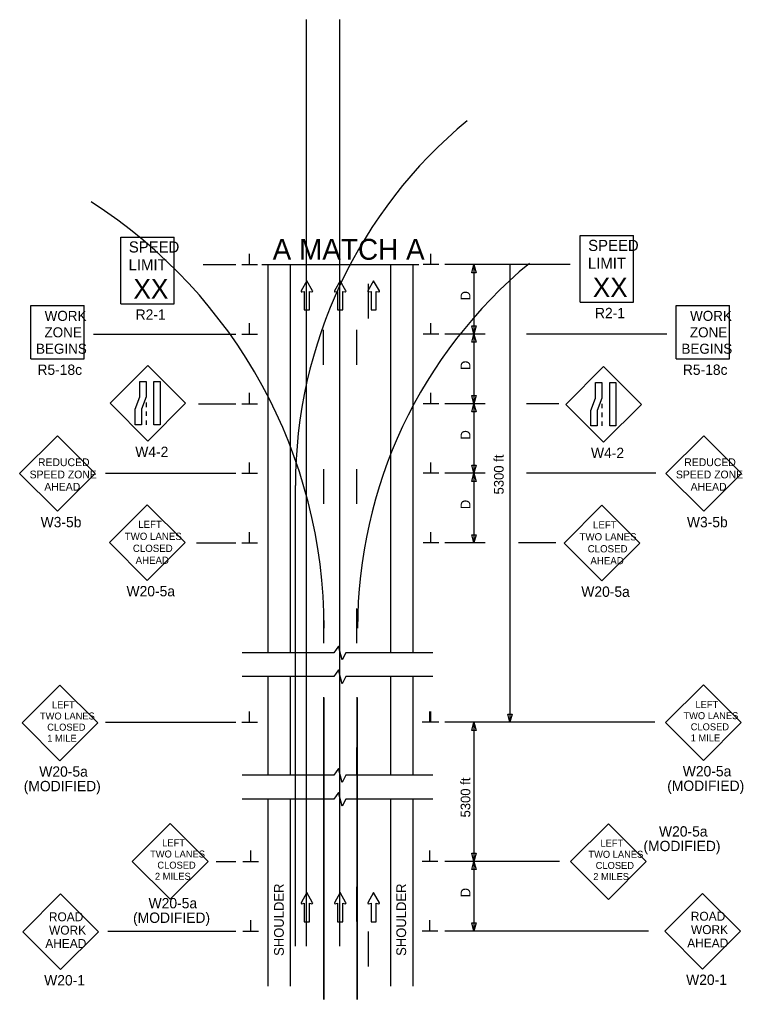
# Model space of a CAD drawing. Extents: x 16728 to 19504, y 5553 to 7079.
# Drawn here: x 17849 to 18369, y 6375 to 7079 of the extents above; entities that cross this region are included whole.
import ezdxf

# ---------------------------------------------------------------- set-up
doc = ezdxf.new("R2010")
doc.units = 0
for name, color, linetype in [('ALI_LEGAL_EX', 7, 'Continuous'), ('MT_SCRATCH_LEVEL_E', 7, 'Continuous'), ('PAVT_EDGE_EX', 7, 'Continuous'), ('TRAFFIC_SIGNS_PR', 7, 'Continuous'), ('TYPICAL_TEXT_DIMEN_PR', 7, 'Continuous')]:
    doc.layers.add(name, color=color, linetype=linetype)

msp = doc.modelspace()

# ---------------------------------------------------------------- linework, layer by layer
at = {"layer": 'ALI_LEGAL_EX'}
for p, q in [((18054.48, 7078.99), (18054.48, 6413.36)), ((18078.48, 7078.99), (18078.48, 6413.36)), ((18054.48, 6981.91), (18054.48, 6413.36)), ((18078.48, 6981.91), (18078.48, 6413.36)), ((18046.81, 6413.36), (18046.81, 6744.25)), ((18067.05, 6592.15), (18067.05, 6515)), ((18067.45, 6375.08), (18067.45, 6591.74)), ((18091.05, 6592.15), (18091.05, 6515)), ((18091.45, 6375.08), (18091.45, 6591.74)), ((18067.05, 6569), (18067.05, 6375.08)), ((18091.05, 6569), (18091.05, 6375.08))]:
    msp.add_line(p, q, dxfattribs=at)
for points in [[(18099.19, 6889.18), (18099.19, 6864.18)], [(18067.05, 6831.03), (18067.05, 6856.03)], [(18091.05, 6831.03), (18091.05, 6856.03)], [(18067.05, 6756.03), (18067.05, 6731.03)], [(18067.05, 6756.03), (18067.05, 6731.03)], [(18091.05, 6731.03), (18091.05, 6756.03)], [(18067.05, 6656.03), (18067.05, 6631.03)], [(18067.05, 6656.03), (18067.05, 6631.03)], [(18091.05, 6631.03), (18091.05, 6656.03)], [(18067.05, 6556.03), (18067.05, 6531.03)], [(18067.05, 6556.03), (18067.05, 6536.14)], [(18091.05, 6536.14), (18091.05, 6556.03)], [(18067.05, 6456.03), (18067.05, 6431.03)], [(18067.05, 6456.03), (18067.05, 6431.03)], [(18091.05, 6431.03), (18091.05, 6456.03)], [(18099.19, 6423.79), (18099.19, 6398.79)]]:
    msp.add_lwpolyline(points, dxfattribs=at)
for centre, radius, start, end in [((18386.81, 6744.25), 340, 129.56655, 180), ((17703.45, 6641.72), 364, 0, 57.29578), ((18431.45, 6641.72), 340, 129.56655, 180)]:
    msp.add_arc(centre, radius, start, end, dxfattribs=at)
at = {"layer": 'MT_SCRATCH_LEVEL_E'}
for p, q in [((18055.05, 6891.26), (18050.94, 6884.02)), ((18059.19, 6884.02), (18055.05, 6891.26)), ((18078.95, 6891.26), (18074.84, 6884.02)), ((18083.1, 6884.02), (18078.95, 6891.26)), ((18103, 6891.26), (18098.89, 6884.02)), ((18107.15, 6884.02), (18103, 6891.26)), ((18051.42, 6883.34), (18053.19, 6883.65)), ((18053.19, 6883.65), (18053.19, 6870.4)), ((18056.94, 6870.4), (18056.94, 6883.65)), ((18056.94, 6883.65), (18058.71, 6883.34)), ((18075.32, 6883.34), (18077.1, 6883.65)), ((18077.1, 6883.65), (18077.1, 6870.4)), ((18080.84, 6870.4), (18080.84, 6883.65)), ((18080.84, 6883.65), (18082.62, 6883.34)), ((18099.37, 6883.34), (18101.15, 6883.65)), ((18101.15, 6883.65), (18101.15, 6870.4)), ((18104.89, 6870.4), (18104.89, 6883.65)), ((18104.89, 6883.65), (18106.67, 6883.34)), ((18053.19, 6870.4), (18056.94, 6870.4)), ((18077.1, 6870.4), (18080.84, 6870.4)), ((18101.15, 6870.4), (18104.89, 6870.4)), ((18055.05, 6451.78), (18050.94, 6444.54)), ((18059.19, 6444.54), (18055.05, 6451.78)), ((18078.95, 6451.78), (18074.84, 6444.54)), ((18083.1, 6444.54), (18078.95, 6451.78)), ((18103, 6451.78), (18098.89, 6444.54)), ((18107.15, 6444.54), (18103, 6451.78)), ((18051.42, 6443.86), (18053.19, 6444.17)), ((18053.19, 6444.17), (18053.19, 6430.92)), ((18056.94, 6430.92), (18056.94, 6444.17)), ((18056.94, 6444.17), (18058.71, 6443.86)), ((18075.32, 6443.86), (18077.1, 6444.17)), ((18077.1, 6444.17), (18077.1, 6430.92)), ((18080.84, 6430.92), (18080.84, 6444.17)), ((18080.84, 6444.17), (18082.62, 6443.86)), ((18099.37, 6443.86), (18101.15, 6444.17)), ((18101.15, 6444.17), (18101.15, 6430.92)), ((18104.89, 6430.92), (18104.89, 6444.17)), ((18104.89, 6444.17), (18106.67, 6443.86)), ((18053.19, 6430.92), (18056.94, 6430.92)), ((18077.1, 6430.92), (18080.84, 6430.92)), ((18101.15, 6430.92), (18104.89, 6430.92))]:
    msp.add_line(p, q, dxfattribs=at)
for centre, start, end in [((18051.34, 6883.8), 150.42484, 279.96381), ((18058.78, 6883.8), 260.03619, 29.77312), ((18075.25, 6883.8), 150.42484, 279.96381), ((18082.69, 6883.8), 260.03619, 29.77312), ((18099.3, 6883.8), 150.42484, 279.96381), ((18106.74, 6883.8), 260.03619, 29.77312), ((18051.34, 6444.32), 150.42484, 279.96381), ((18058.78, 6444.32), 260.03619, 29.77312), ((18075.25, 6444.32), 150.42484, 279.96381), ((18082.69, 6444.32), 260.03619, 29.77312), ((18099.3, 6444.32), 150.42484, 279.96381), ((18106.74, 6444.32), 260.03619, 29.77312)]:
    msp.add_arc(centre, 0.463, start, end, dxfattribs=at)
at = {"layer": 'PAVT_EDGE_EX'}
for p, q in [((18027.05, 6903.04), (18027.05, 6624.09)), ((18043.05, 6903.04), (18043.05, 6624.09)), ((18115.05, 6903.04), (18115.05, 6624.09)), ((18131.05, 6903.04), (18131.05, 6624.09)), ((18027.05, 6606.96), (18027.05, 6536.14)), ((18043.05, 6606.96), (18043.05, 6536.14)), ((18115.05, 6606.96), (18115.05, 6536.14)), ((18131.05, 6606.96), (18131.05, 6536.14)), ((18027.05, 6519), (18027.05, 6384.62)), ((18043.05, 6519), (18043.05, 6384.62)), ((18115.05, 6519), (18115.05, 6384.62)), ((18131.05, 6519), (18131.05, 6384.62))]:
    msp.add_line(p, q, dxfattribs=at)
at = {"layer": 'TRAFFIC_SIGNS_PR'}
for p, q in [((17921.38, 6922.8), (17959.78, 6922.8)), ((17921.38, 6874.8), (17921.38, 6922.8)), ((17959.78, 6874.8), (17959.78, 6922.8)), ((18251.35, 6923.9), (18289.74, 6923.9)), ((18251.35, 6875.9), (18251.35, 6923.9)), ((18289.74, 6875.9), (18289.74, 6923.9)), ((17856.68, 6835.18), (17856.68, 6873.58)), ((17856.68, 6873.58), (17895.08, 6873.58)), ((17895.08, 6835.18), (17895.08, 6873.58)), ((17921.38, 6874.8), (17959.78, 6874.8)), ((18251.35, 6875.9), (18289.74, 6875.9)), ((18320.32, 6835.18), (18320.32, 6873.58)), ((18320.32, 6873.58), (18358.72, 6873.58)), ((18358.72, 6835.18), (18358.72, 6873.58)), ((17856.68, 6835.18), (17895.08, 6835.18)), ((18320.32, 6835.18), (18358.72, 6835.18)), ((17940.82, 6830.49), (17913.67, 6803.34)), ((17967.97, 6803.34), (17940.82, 6830.49)), ((18268.18, 6829.71), (18241.02, 6802.55)), ((18295.33, 6802.55), (18268.18, 6829.71)), ((17913.67, 6803.34), (17940.82, 6776.19)), ((17939.57, 6803.83), (17939.57, 6800.63)), ((17940.82, 6776.19), (17967.97, 6803.34)), ((18241.02, 6802.55), (18268.18, 6775.4)), ((18266.93, 6803.04), (18266.93, 6799.84)), ((18268.18, 6775.4), (18295.33, 6802.55)), ((17939.57, 6797.43), (17939.57, 6794.23)), ((18266.93, 6796.64), (18266.93, 6793.44)), ((17939.57, 6791.03), (17939.57, 6787.83)), ((18266.93, 6790.24), (18266.93, 6787.04)), ((17875.83, 6780.04), (17848.68, 6752.88)), ((17902.98, 6752.88), (17875.83, 6780.04)), ((18340.11, 6780.04), (18312.95, 6752.88)), ((18367.26, 6752.88), (18340.11, 6780.04)), ((17848.68, 6752.88), (17875.83, 6725.73)), ((17875.83, 6725.73), (17902.98, 6752.88)), ((18312.95, 6752.88), (18340.11, 6725.73)), ((18340.11, 6725.73), (18367.26, 6752.88)), ((17940.35, 6730.38), (17913.19, 6703.23)), ((17967.5, 6703.23), (17940.35, 6730.38)), ((18267.04, 6730.04), (18239.89, 6702.88)), ((18294.2, 6702.88), (18267.04, 6730.04)), ((17913.19, 6703.23), (17940.35, 6676.08)), ((17940.35, 6676.08), (17967.5, 6703.23)), ((18239.89, 6702.88), (18267.04, 6675.73)), ((18267.04, 6675.73), (18294.2, 6702.88)), ((17877.69, 6600.88), (17850.5, 6573.69)), ((17904.87, 6573.69), (17877.69, 6600.88)), ((18339.95, 6601.12), (18312.76, 6573.93)), ((18367.13, 6573.93), (18339.95, 6601.12)), ((17850.5, 6573.69), (17877.69, 6546.51)), ((17877.69, 6546.51), (17904.87, 6573.69)), ((18312.76, 6573.93), (18339.95, 6546.75)), ((18339.95, 6546.75), (18367.13, 6573.93)), ((17956.83, 6501.43), (17929.65, 6474.24)), ((17984.02, 6474.24), (17956.83, 6501.43)), ((18271.69, 6501.23), (18244.5, 6474.05)), ((18298.88, 6474.05), (18271.69, 6501.23)), ((17929.65, 6474.24), (17956.83, 6447.06)), ((17956.83, 6447.06), (17984.02, 6474.24)), ((18244.5, 6474.05), (18271.69, 6446.86)), ((18271.69, 6446.86), (18298.88, 6474.05)), ((17878.17, 6450.86), (17851.02, 6423.71)), ((17905.33, 6423.71), (17878.17, 6450.86)), ((18339.32, 6451.23), (18312.17, 6424.07)), ((18366.47, 6424.07), (18339.32, 6451.23)), ((17851.02, 6423.71), (17878.17, 6396.56)), ((17878.17, 6396.56), (17905.33, 6423.71)), ((18312.17, 6424.07), (18339.32, 6396.92)), ((18339.32, 6396.92), (18366.47, 6424.07))]:
    msp.add_line(p, q, dxfattribs=at)
for points in [[(17939.57, 6819.08), (17939.57, 6807.89), (17936.23, 6799.01), (17936.23, 6787.83), (17931.73, 6787.83), (17931.73, 6799.01), (17935.08, 6807.89), (17935.08, 6819.08)], [(17949.71, 6819.08), (17949.71, 6787.83), (17945.21, 6787.83), (17945.21, 6819.08)], [(18266.93, 6818.29), (18266.93, 6807.11), (18263.58, 6798.23), (18263.58, 6787.04), (18259.09, 6787.04), (18259.09, 6798.23), (18262.43, 6807.11), (18262.43, 6818.29)], [(18277.06, 6818.29), (18277.06, 6787.04), (18272.57, 6787.04), (18272.57, 6818.29)]]:
    msp.add_lwpolyline(points, close=True, dxfattribs=at)
at = {"layer": 'TYPICAL_TEXT_DIMEN_PR'}
for p, q in [((18013.92, 6903.04), (18013.92, 6910.83)), ((18144.17, 6903.04), (18144.17, 6910.83)), ((17980.58, 6903.04), (18004.05, 6903.04)), ((18008.3, 6903.04), (18019.55, 6903.04)), ((18022.72, 6903.04), (18135.37, 6903.04)), ((18149.8, 6903.04), (18138.55, 6903.04)), ((18244.27, 6903.04), (18154.05, 6903.04)), ((18173.48, 6897.18), (18175.05, 6903.04)), ((18175.05, 6903.04), (18175.05, 6853.04)), ((18175.05, 6903.04), (18176.62, 6897.18)), ((18200.89, 6903.04), (18200.89, 6574.2)), ((18175.05, 6897.18), (18173.48, 6897.18)), ((18176.62, 6897.18), (18175.05, 6897.18)), ((18013.92, 6853.04), (18013.92, 6860.83)), ((18144.17, 6853.04), (18144.17, 6860.83)), ((18175.05, 6853.04), (18173.48, 6858.91)), ((18173.48, 6858.91), (18175.05, 6858.91)), ((18175.05, 6858.91), (18176.62, 6858.91)), ((18176.62, 6858.91), (18175.05, 6853.04)), ((17901.65, 6853.04), (18004.05, 6853.04)), ((18008.3, 6853.04), (18019.55, 6853.04)), ((18149.8, 6853.04), (18138.55, 6853.04)), ((18183.05, 6853.04), (18154.05, 6853.04)), ((18173.48, 6847.18), (18175.05, 6853.04)), ((18175.05, 6853.04), (18175.05, 6803.04)), ((18175.05, 6853.04), (18176.62, 6847.18)), ((18313.58, 6853.04), (18212.91, 6853.04)), ((18175.05, 6847.18), (18173.48, 6847.18)), ((18176.62, 6847.18), (18175.05, 6847.18)), ((18013.92, 6803.04), (18013.92, 6810.83)), ((18144.17, 6803.04), (18144.17, 6810.83)), ((18175.05, 6803.04), (18173.48, 6808.91)), ((18173.48, 6808.91), (18175.05, 6808.91)), ((18175.05, 6808.91), (18176.62, 6808.91)), ((18176.62, 6808.91), (18175.05, 6803.04)), ((17977.25, 6803.04), (18004.05, 6803.04)), ((18008.3, 6803.04), (18019.55, 6803.04)), ((18149.8, 6803.04), (18138.55, 6803.04)), ((18183.05, 6803.04), (18154.05, 6803.04)), ((18173.48, 6797.18), (18175.05, 6803.04)), ((18175.05, 6803.04), (18175.05, 6753.04)), ((18175.05, 6803.04), (18176.62, 6797.18)), ((18235.99, 6803.04), (18212.91, 6803.04)), ((18175.05, 6797.18), (18173.48, 6797.18)), ((18176.62, 6797.18), (18175.05, 6797.18)), ((18013.92, 6753.04), (18013.92, 6760.83)), ((18144.17, 6753.04), (18144.17, 6760.83)), ((18175.05, 6753.04), (18173.48, 6758.91)), ((18173.48, 6758.91), (18175.05, 6758.91)), ((18175.05, 6758.91), (18176.62, 6758.91)), ((18176.62, 6758.91), (18175.05, 6753.04)), ((17910.5, 6753.04), (18004.05, 6753.04)), ((18008.3, 6753.04), (18019.55, 6753.04)), ((18149.8, 6753.04), (18138.55, 6753.04)), ((18183.05, 6753.04), (18154.05, 6753.04)), ((18173.48, 6747.18), (18175.05, 6753.04)), ((18175.05, 6753.04), (18175.05, 6703.04)), ((18175.05, 6753.04), (18176.62, 6747.18)), ((18305.81, 6753.04), (18212.91, 6753.04)), ((18175.05, 6747.18), (18173.48, 6747.18)), ((18176.62, 6747.18), (18175.05, 6747.18)), ((18013.92, 6703.04), (18013.92, 6710.83)), ((18144.17, 6703.04), (18144.17, 6710.83)), ((18175.05, 6703.04), (18173.48, 6708.91)), ((18173.48, 6708.91), (18175.05, 6708.91)), ((18175.05, 6708.91), (18176.62, 6708.91)), ((18176.62, 6708.91), (18175.05, 6703.04)), ((17975.68, 6703.04), (18004.05, 6703.04)), ((18008.3, 6703.04), (18019.55, 6703.04)), ((18149.8, 6703.04), (18138.55, 6703.04)), ((18183.05, 6703.04), (18154.05, 6703.04)), ((18233.85, 6703.04), (18206.97, 6703.04)), ((18074.4, 6624.09), (18008.45, 6624.09)), ((18077.65, 6628.89), (18074.4, 6624.09)), ((18080.39, 6618.95), (18077.65, 6628.89)), ((18083.14, 6624.09), (18080.39, 6618.95)), ((18145.47, 6624.09), (18083.14, 6624.09)), ((18077.65, 6611.76), (18074.4, 6606.96)), ((18080.39, 6601.82), (18077.65, 6611.76)), ((18074.4, 6606.96), (18008.45, 6606.96)), ((18083.14, 6606.96), (18080.39, 6601.82)), ((18145.47, 6606.96), (18083.14, 6606.96)), ((18013.92, 6574.2), (18013.92, 6581.98)), ((18143.42, 6574.2), (18143.42, 6581.98)), ((18144.17, 6574.2), (18144.17, 6581.98)), ((18200.89, 6574.2), (18199.32, 6580.06)), ((18199.32, 6580.06), (18200.89, 6580.06)), ((18200.89, 6580.06), (18202.46, 6580.06)), ((18202.46, 6580.06), (18200.89, 6574.2)), ((17910.3, 6574.2), (18004.05, 6574.2)), ((18008.3, 6574.2), (18019.55, 6574.2)), ((18149.05, 6574.2), (18137.8, 6574.2)), ((18149.8, 6574.2), (18138.55, 6574.2)), ((18304.94, 6574.2), (18154.05, 6574.2)), ((18173.48, 6568.34), (18175.05, 6574.2)), ((18175.05, 6568.34), (18173.48, 6568.34)), ((18175.05, 6574.2), (18175.05, 6474.2)), ((18175.05, 6574.2), (18176.62, 6568.34)), ((18176.62, 6568.34), (18175.05, 6568.34)), ((18077.65, 6540.94), (18074.4, 6536.14)), ((18080.39, 6531), (18077.65, 6540.94)), ((18074.4, 6536.14), (18008.45, 6536.14)), ((18083.14, 6536.14), (18080.39, 6531)), ((18145.47, 6536.14), (18083.14, 6536.14)), ((18074.4, 6519), (18008.45, 6519)), ((18077.65, 6523.8), (18074.4, 6519)), ((18080.39, 6513.86), (18077.65, 6523.8)), ((18083.14, 6519), (18080.39, 6513.86)), ((18145.47, 6519), (18083.14, 6519)), ((18014.67, 6474.2), (18014.67, 6481.98)), ((18143.42, 6474.2), (18143.42, 6481.98)), ((18175.05, 6474.2), (18173.48, 6480.06)), ((18173.48, 6480.06), (18175.05, 6480.06)), ((18175.05, 6480.06), (18176.62, 6480.06)), ((18176.62, 6480.06), (18175.05, 6474.2)), ((17989.86, 6474.12), (18004.05, 6474.12)), ((18009.05, 6474.2), (18020.3, 6474.2)), ((18149.05, 6474.2), (18137.8, 6474.2)), ((18236.52, 6474.2), (18154.05, 6474.2)), ((18173.48, 6468.34), (18175.05, 6474.2)), ((18175.05, 6474.2), (18175.05, 6424.2)), ((18175.05, 6474.2), (18176.62, 6468.34)), ((18175.05, 6468.34), (18173.48, 6468.34)), ((18176.62, 6468.34), (18175.05, 6468.34)), ((18014.67, 6424.2), (18014.67, 6431.98)), ((18143.42, 6424.2), (18143.42, 6431.98)), ((18175.05, 6424.2), (18173.48, 6430.06)), ((18173.48, 6430.06), (18175.05, 6430.06)), ((18175.05, 6430.06), (18176.62, 6430.06)), ((18176.62, 6430.06), (18175.05, 6424.2)), ((17912.07, 6424.2), (18004.05, 6424.2)), ((18009.05, 6424.2), (18020.3, 6424.2)), ((18149.05, 6424.2), (18137.8, 6424.2)), ((18300.5, 6424.2), (18154.05, 6424.2))]:
    msp.add_line(p, q, dxfattribs=at)

# ---------------------------------------------------------------- texts
at = {"layer": 'TRAFFIC_SIGNS_PR'}
for s, height, p in [('SPEED', 8, (17927.14, 6911.66)), ('SPEED', 8, (18257.11, 6912.77)), ('LIMIT', 8, (17926.98, 6898.86)), ('LIMIT', 8, (18256.95, 6899.97)), ('XX', 14.031, (17930.49, 6878.56)), ('XX', 14.031, (18260.46, 6879.66)), ('R2-1', 7.44, (17932.05, 6863.36)), ('R2-1', 7.44, (18262.02, 6864.47)), ('WORK', 7.217, (17866.68, 6862.54)), ('WORK', 7.217, (18330.32, 6862.54)), ('ZONE', 7.217, (17866.56, 6850.73)), ('ZONE', 7.217, (18330.2, 6850.73)), ('BEGINS', 7.217, (17860.49, 6838.93)), ('BEGINS', 7.217, (18324.13, 6838.93)), ('R5-18c', 7.44, (17861.49, 6823.74)), ('R5-18c', 7.44, (18325.13, 6823.74)), ('W4-2', 7.44, (17931.78, 6764.75)), ('W4-2', 7.44, (18259.13, 6763.96)), ('REDUCED', 5.6, (17861.89, 6758.19)), ('REDUCED', 5.6, (18326.16, 6758.19)), ('SPEED ZONE', 5.6, (17855.88, 6749.39)), ('SPEED ZONE', 5.6, (18320.16, 6749.39)), ('AHEAD', 5.6, (17866.44, 6740.59)), ('AHEAD', 5.6, (18330.72, 6740.59)), ('W3-5b', 7.44, (17863.79, 6714.29)), ('LEFT', 5.2, (17933.88, 6713.77)), ('LEFT', 5.2, (18260.58, 6713.43)), ('W3-5b', 7.44, (18328.06, 6714.29)), ('TWO LANES', 5.2, (17924.21, 6705.17)), ('TWO LANES', 5.2, (18250.91, 6704.83)), ('CLOSED', 5.2, (17930.06, 6696.57)), ('CLOSED', 5.2, (18256.76, 6696.23)), ('AHEAD', 5.2, (17932.01, 6687.97)), ('AHEAD', 5.2, (18258.71, 6687.63)), ('W20-5a', 7.44, (17925.49, 6664.64)), ('W20-5a', 7.44, (18252.19, 6664.3)), ('LEFT', 5.006, (17871.93, 6584.19)), ('LEFT', 5.006, (18334.19, 6584.43)), ('TWO LANES', 5.006, (17863.28, 6576.18)), ('TWO LANES', 5.006, (18325.54, 6576.42)), ('CLOSED', 5.006, (17868.51, 6568.17)), ('CLOSED', 5.006, (18330.77, 6568.41)), ('1 MILE', 5.006, (17868.5, 6560.16)), ('1 MILE', 5.006, (18330.76, 6560.4)), ('W20-5a', 7.449, (17862.81, 6535.06)), ('W20-5a', 7.449, (18325.07, 6535.29)), ('(MODIFIED)', 7.449, (17851.65, 6524.61)), ('(MODIFIED)', 7.449, (18313.91, 6524.84)), ('W20-5a', 7.449, (18307.98, 6492.05)), ('LEFT', 5.006, (17951.08, 6485.04)), ('LEFT', 5.006, (18265.93, 6484.84)), ('(MODIFIED)', 7.449, (18296.82, 6481.59)), ('TWO LANES', 5.006, (17942.42, 6477.03)), ('TWO LANES', 5.006, (18257.28, 6476.83)), ('CLOSED', 5.006, (17947.66, 6469.02)), ('CLOSED', 5.006, (18262.51, 6468.82)), ('2 MILES', 5.006, (17945.9, 6461.02)), ('2 MILES', 5.006, (18260.76, 6460.82)), ('W20-5a', 7.449, (17941.33, 6440.49)), ('ROAD', 6.4, (17869.71, 6431.24)), ('(MODIFIED)', 7.449, (17930.17, 6430.04)), ('ROAD', 6.4, (18330.86, 6431.61)), ('WORK', 6.4, (17869.82, 6421.64)), ('WORK', 6.4, (18330.97, 6422.01)), ('AHEAD', 6.4, (17867.13, 6412.04)), ('AHEAD', 6.4, (18328.28, 6412.41)), ('W20-1', 7.44, (17866.34, 6385.12)), ('W20-1', 7.44, (18327.49, 6385.48))]:
    msp.add_text(s, height=height, dxfattribs=at).set_placement(p)
at = {"layer": 'TYPICAL_TEXT_DIMEN_PR'}
msp.add_text('A MATCH A', height=15, dxfattribs=at).set_placement((18030.46, 6906.45))
for s, p in [('D', (18172.49, 6877.26)), ('D', (18172.49, 6827.26)), ('D', (18172.49, 6777.26)), ('5300 ft', (18196.43, 6737.84)), ('D', (18172.49, 6727.26)), ('5300 ft', (18172.49, 6505.81)), ('SHOULDER', (18038.47, 6406.33)), ('SHOULDER', (18126.33, 6406.33)), ('D', (18172.49, 6448.42))]:
    msp.add_text(s, height=7, rotation=90, dxfattribs=at).set_placement(p)

doc.saveas('drawing.dxf')
